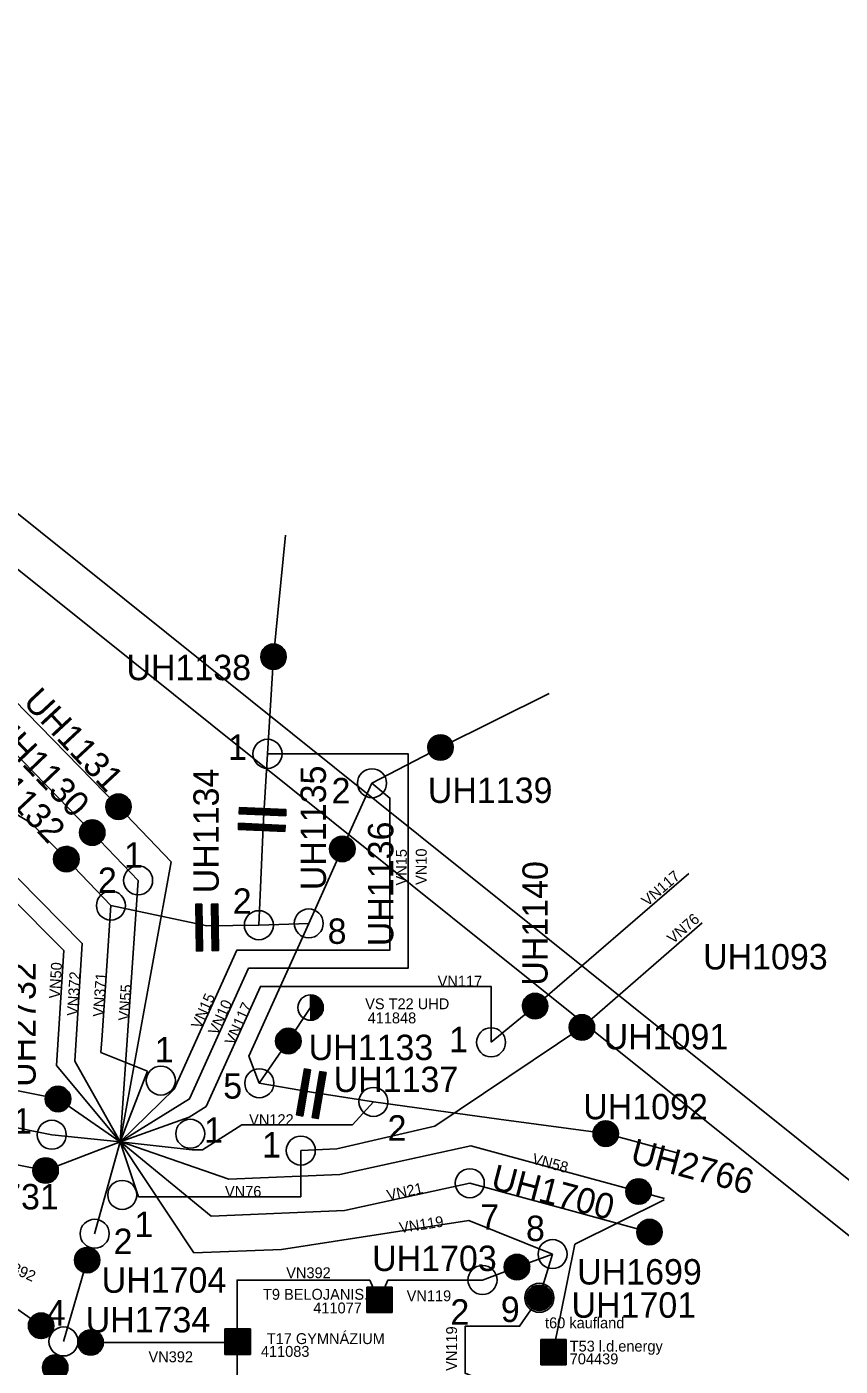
# Model space of a CAD drawing. Extents: x -541654 to -535721, y -1185255 to -1179094.
# Drawn here: x -537653 to -536532, y -1180940 to -1179094 of the extents above; entities that cross this region are included whole.
import ezdxf

# ---------------------------------------------------------------- set-up
doc = ezdxf.new("R2010")
doc.units = 0
for name, color, linetype in [('Default', 7, 'Continuous'), ('Vrstva 1', 7, 'Continuous'), ('Vrstva 2', 7, 'Continuous'), ('Vrstva 3', 7, 'Continuous'), ('Vrstva 5', 7, 'Continuous')]:
    doc.layers.add(name, color=color, linetype=linetype)

# ---------------------------------------------------------------- blocks, each defined once
blk = doc.blocks.new('PS100')
at = {"layer": 'Default'}
for p, q in [((-17.5, -0.7), (0.7, 17.5)), ((-17.5, 0.7), (-0.7, 17.5)), ((-17.4, -2), (2, 17.4)), ((-17.3, 2.2), (-2.2, 17.3)), ((-17.2, -3.3), (3.3, 17.2)), ((-17, 4), (-4, 17)), ((-16.9, -4.4), (4.4, 16.9)), ((-16.6, -5.5), (5.5, 16.6)), ((-16.4, 6), (-6, 16.4)), ((-16.2, -6.5), (6.5, 16.2)), ((-15.8, -7.5), (7.5, 15.8)), ((-15.3, -8.4), (8.4, 15.3)), ((-15.2, 8.6), (-8.6, 15.2)), ((-14.8, -9.3), (9.3, 14.8)), ((-14.2, -10.2), (10.2, 14.2)), ((-13.6, -11), (11, 13.6)), ((-13, -11.7), (11.7, 13)), ((-12.3, -12.5), (12.5, 12.3)), ((-11.5, -13.2), (13.2, 11.5)), ((-10.8, -13.8), (13.8, 10.8)), ((-9.9, -14.4), (14.4, 9.9)), ((-9.1, -14.9), (14.9, 9.1)), ((-8.2, -15.5), (15.5, 8.2)), ((-7.2, -15.9), (15.9, 7.2)), ((-6.2, -16.3), (16.3, 6.2)), ((-5.2, -16.7), (16.7, 5.2)), ((-4.1, -17), (17, 4.1)), ((-2.9, -17.2), (17.2, 2.9)), ((-1.6, -17.4), (17.4, 1.6)), ((-0.3, -17.5), (17.5, 0.3)), ((1.1, -17.4), (17.4, -1.1)), ((2.7, -17.3), (17.3, -2.7)), ((4.5, -16.9), (16.9, -4.5)), ((6.7, -16.2), (16.2, -6.7)), ((9.7, -14.5), (14.5, -9.7))]:
    blk.add_line(p, q, dxfattribs=at)
blk.add_circle((0, 0), 17.5, dxfattribs=at)
blk = doc.blocks.new('PS140')
at = {"layer": 'Default'}
for p, q in [((-17.5, 0), (0, 17.5)), ((-17.4, -1.4), (1.4, 17.4)), ((-17.4, 1.5), (-1.5, 17.4)), ((-17.3, -2.6), (2.6, 17.3)), ((-17.2, 3.1), (-3.1, 17.2)), ((-17.1, -3.8), (3.8, 17.1)), ((-16.8, -4.9), (4.9, 16.8)), ((-16.8, 5), (-5, 16.8)), ((-16.4, -6), (6, 16.4)), ((-16, -7), (7, 16)), ((-15.9, 7.2), (-7.2, 15.9)), ((-15.6, -8), (8, 15.6)), ((-15.1, -8.9), (8.9, 15.1)), ((-14.5, -9.8), (9.8, 14.5)), ((-13.9, -10.6), (10.6, 13.9)), ((-13.8, 10.8), (-10.8, 13.8)), ((-13.3, -11.4), (11.4, 13.3)), ((-12.6, -12.1), (12.1, 12.6)), ((-11.9, -12.8), (12.8, 11.9)), ((-11.2, -13.5), (13.5, 11.2)), ((-10.4, -14.1), (14.1, 10.4)), ((-9.5, -14.7), (14.7, 9.5)), ((-8.6, -15.2), (15.2, 8.6)), ((-7.7, -15.7), (15.7, 7.7)), ((-6.7, -16.1), (16.1, 6.7)), ((-5.7, -16.5), (16.5, 5.7)), ((-4.6, -16.9), (16.9, 4.6)), ((-3.5, -17.1), (17.1, 3.5)), ((-2.3, -17.3), (17.3, 2.3)), ((-1, -17.5), (17.5, 1)), ((0.4, -17.5), (17.5, -0.4)), ((1.9, -17.4), (17.4, -1.9)), ((3.6, -17.1), (17.1, -3.6)), ((5.5, -16.6), (16.6, -5.5)), ((8, -15.6), (15.6, -8))]:
    blk.add_line(p, q, dxfattribs=at)
blk.add_circle((0, 0), 17.5, dxfattribs=at)
blk = doc.blocks.new('PS150')
at = {"layer": 'Default'}
for p, q in [((-15.1, 22.4), (-7.4, 30.1)), ((-15.1, 23.8), (-8.8, 30.1)), ((-15.1, 25.2), (-10.2, 30.1)), ((-15.1, 26.6), (-11.6, 30.1)), ((-15.1, 28), (-13, 30.1)), ((-15.1, 29.4), (-14.4, 30.1)), ((-15.1, 20.9), (-6.5, 29.5)), ((-15.1, 19.5), (-6.5, 28.1)), ((-15.1, 18.1), (-6.5, 26.7)), ((-15.1, 16.7), (-6.5, 25.3)), ((-15.1, 15.3), (-6.5, 23.9)), ((-15.1, 13.9), (-6.5, 22.4)), ((-15.1, 12.5), (-6.5, 21)), ((-15.1, 11), (-6.5, 19.6)), ((6.7, 22.6), (14.1, 30.1)), ((6.7, 24), (12.7, 30.1)), ((6.7, 25.4), (11.3, 30.1)), ((6.7, 26.8), (9.9, 30.1)), ((6.7, 28.3), (8.5, 30.1)), ((6.7, 29.7), (7, 30.1)), ((6.7, 21.2), (15.2, 29.8)), ((6.7, 19.8), (15.2, 28.3)), ((6.7, 18.4), (15.2, 26.9)), ((6.7, 16.9), (15.2, 25.5)), ((6.7, 15.5), (15.2, 24.1)), ((6.7, 14.1), (15.2, 22.7)), ((6.7, 12.7), (15.2, 21.3)), ((6.7, 11.3), (15.2, 19.9)), ((-15.1, 9.6), (-6.5, 18.2)), ((-15.1, 8.2), (-6.5, 16.8)), ((-15.1, 6.8), (-6.5, 15.4)), ((-15.1, 5.4), (-6.5, 14)), ((-15.1, 4), (-6.5, 12.5)), ((-15.1, 2.6), (-6.5, 11.1)), ((-15.1, 1.2), (-6.5, 9.7)), ((-15.1, -0.3), (-6.5, 8.3)), ((-15.1, -1.7), (-6.5, 6.9)), ((-15.1, -3.1), (-6.5, 5.5)), ((-15.1, -4.5), (-6.5, 4.1)), ((-15.1, -5.9), (-6.5, 2.6)), ((-15.1, -7.3), (-6.5, 1.2)), ((6.7, 9.9), (15.2, 18.4)), ((6.7, 8.5), (15.2, 17)), ((6.7, 7.1), (15.2, 15.6)), ((6.7, 5.6), (15.2, 14.2)), ((6.7, 4.2), (15.2, 12.8)), ((6.7, 2.8), (15.2, 11.4)), ((6.7, 1.4), (15.2, 10)), ((6.7, 0), (15.2, 8.5)), ((6.7, -1.4), (15.2, 7.1)), ((6.7, -2.8), (15.2, 5.7)), ((6.7, -4.3), (15.2, 4.3)), ((6.7, -5.7), (15.2, 2.9)), ((6.7, -7.1), (15.2, 1.5)), ((6.7, -8.5), (15.2, 0.1)), ((-15.1, -8.7), (-6.5, -0.2)), ((-15.1, -10.2), (-6.5, -1.6)), ((-15.1, -11.6), (-6.5, -3)), ((-15.1, -13), (-6.5, -4.4)), ((-15.1, -14.4), (-6.5, -5.8)), ((-15.1, -15.8), (-6.5, -7.3)), ((-15.1, -17.2), (-6.5, -8.7)), ((-15.1, -18.6), (-6.5, -10.1)), ((-15.1, -20.1), (-6.5, -11.5)), ((-15.1, -21.5), (-6.5, -12.9)), ((-15.1, -22.9), (-6.5, -14.3)), ((-15.1, -24.3), (-6.5, -15.7)), ((-15.1, -25.7), (-6.5, -17.2)), ((6.7, -9.9), (15.2, -1.4)), ((6.7, -11.3), (15.2, -2.8)), ((6.7, -12.7), (15.2, -4.2)), ((6.7, -14.2), (15.2, -5.6)), ((6.7, -15.6), (15.2, -7)), ((6.7, -17), (15.2, -8.4)), ((6.7, -18.4), (15.2, -9.8)), ((6.7, -19.8), (15.2, -11.3)), ((6.7, -21.2), (15.2, -12.7)), ((6.7, -22.6), (15.2, -14.1)), ((6.7, -24.1), (15.2, -15.5)), ((6.7, -25.5), (15.2, -16.9)), ((6.7, -26.9), (15.2, -18.3)), ((-15.1, -27.1), (-6.5, -18.6)), ((-15.1, -28.5), (-6.5, -20)), ((-15.1, -30), (-6.5, -21.4)), ((-15.1, -31.4), (-6.5, -22.8)), ((-15.1, -32.8), (-6.5, -24.2)), ((-15, -34.2), (-6.5, -25.6)), ((-13.6, -34.2), (-6.5, -27.1)), ((-12.2, -34.2), (-6.5, -28.5)), ((-10.8, -34.2), (-6.5, -29.9)), ((-9.4, -34.2), (-6.5, -31.3)), ((-8, -34.2), (-6.5, -32.7)), ((-6.5, -34.2), (-6.5, -34.1)), ((6.7, -28.3), (15.2, -19.7)), ((6.7, -29.7), (15.2, -21.2)), ((6.7, -31.1), (15.2, -22.6)), ((6.7, -32.5), (15.2, -24)), ((6.7, -34), (15.2, -25.4)), ((7.9, -34.2), (15.2, -26.8)), ((9.3, -34.2), (15.2, -28.2)), ((10.7, -34.2), (15.2, -29.6)), ((12.1, -34.2), (15.2, -31)), ((13.5, -34.2), (15.2, -32.5)), ((14.9, -34.2), (15.2, -33.9))]:
    blk.add_line(p, q, dxfattribs=at)
for points in [[(-6.5, 30.1), (-6.5, -34.2), (-15.1, -34.2), (-15.1, 30.1)], [(15.2, 30.1), (15.2, -34.2), (6.7, -34.2), (6.7, 30.1)]]:
    blk.add_lwpolyline(points, close=True, dxfattribs=at)
blk = doc.blocks.new('PS610')
at = {"layer": 'Default'}
for p, q in [((0, 16.2), (1.3, 17.4)), ((0, 14.7), (2.5, 17.3)), ((0, 13.3), (3.7, 17.1)), ((0, 11.9), (4.9, 16.8)), ((0, 10.5), (5.9, 16.4)), ((0, 9.1), (7, 16)), ((0, 7.7), (7.9, 15.6)), ((0, 6.3), (8.8, 15.1)), ((0, 4.8), (9.7, 14.5)), ((0, 3.4), (10.5, 14)), ((0, 2), (11.3, 13.3)), ((0, 0.6), (12, 12.7)), ((0, -0.8), (12.8, 12)), ((0, -2.2), (13.4, 11.2)), ((0, -3.6), (14, 10.4)), ((0, -5), (14.6, 9.6)), ((0, -6.5), (15.2, 8.7)), ((0, -7.9), (15.6, 7.8)), ((0, -9.3), (16.1, 6.8)), ((0, -10.7), (16.5, 5.8)), ((0, -12.1), (16.8, 4.7)), ((0, -13.5), (17.1, 3.6)), ((0, -14.9), (17.3, 2.4)), ((0, -16.4), (17.4, 1.1)), ((0.3, -17.5), (17.5, -0.3)), ((1.8, -17.4), (17.4, -1.8)), ((3.5, -17.1), (17.1, -3.5)), ((5.4, -16.7), (16.7, -5.4)), ((7.8, -15.7), (15.6, -7.8))]:
    blk.add_line(p, q, dxfattribs=at)
blk.add_lwpolyline([(0, 17.5), (0, -17.5)], dxfattribs=at)
blk.add_circle((0, 0), 17.5, dxfattribs=at)
blk = doc.blocks.new('PS800')
at = {"layer": 'Vrstva 2'}
blk.add_circle((0, 0), 20, dxfattribs=at)
blk = doc.blocks.new('PS630')
at = {"layer": 'Default'}
for p, q in [((-16.6, -14.9), (17.1, 18.7)), ((-16.6, -13.5), (15.7, 18.7)), ((-16.6, -12.1), (14.2, 18.7)), ((-16.6, -10.7), (12.8, 18.7)), ((-16.6, -9.3), (11.4, 18.7)), ((-16.6, -7.9), (10, 18.7)), ((-16.6, -6.5), (8.6, 18.7)), ((-16.6, -5), (7.2, 18.7)), ((-16.6, -3.6), (5.8, 18.7)), ((-16.6, -2.2), (4.3, 18.7)), ((-16.6, -0.8), (2.9, 18.7)), ((-16.6, 0.6), (1.5, 18.7)), ((-16.6, 2), (0.1, 18.7)), ((-16.6, 3.4), (-1.3, 18.7)), ((-16.6, 4.9), (-2.7, 18.7)), ((-16.6, 6.3), (-4.1, 18.7)), ((-16.6, 7.7), (-5.6, 18.7)), ((-16.6, 9.1), (-7, 18.7)), ((-16.6, 10.5), (-8.4, 18.7)), ((-16.6, 11.9), (-9.8, 18.7)), ((-16.6, 13.3), (-11.2, 18.7)), ((-16.6, 14.8), (-12.6, 18.7)), ((-16.6, 16.2), (-14, 18.7)), ((-16.6, 17.6), (-15.5, 18.7)), ((-16.5, -16.3), (18.4, 18.6)), ((-15.1, -16.3), (18.4, 17.2)), ((-13.7, -16.3), (18.4, 15.8)), ((-12.3, -16.3), (18.4, 14.4)), ((-10.9, -16.3), (18.4, 13)), ((-9.4, -16.3), (18.4, 11.6)), ((-8, -16.3), (18.4, 10.2)), ((-6.6, -16.3), (18.4, 8.7)), ((-5.2, -16.3), (18.4, 7.3)), ((-3.8, -16.3), (18.4, 5.9)), ((-2.4, -16.3), (18.4, 4.5)), ((-1, -16.3), (18.4, 3.1)), ((0.5, -16.3), (18.4, 1.7)), ((1.9, -16.3), (18.4, 0.3)), ((3.3, -16.3), (18.4, -1.2)), ((4.7, -16.3), (18.4, -2.6)), ((6.1, -16.3), (18.4, -4)), ((7.5, -16.3), (18.4, -5.4)), ((8.9, -16.3), (18.4, -6.8)), ((10.4, -16.3), (18.4, -8.2)), ((11.8, -16.3), (18.4, -9.6)), ((13.2, -16.3), (18.4, -11.1)), ((14.6, -16.3), (18.4, -12.5)), ((16, -16.3), (18.4, -13.9)), ((17.4, -16.3), (18.4, -15.3))]:
    blk.add_line(p, q, dxfattribs=at)
for points in [[(-16.6, 18.7), (-16.6, -16.3)], [(18.4, 18.7), (-16.6, 18.7)], [(-16.6, 18.7), (-16.6, -16.3)], [(18.4, -16.3), (18.4, 18.7)], [(-16.6, -16.3), (18.4, -16.3)]]:
    blk.add_lwpolyline(points, dxfattribs=at)

msp = doc.modelspace()

# ---------------------------------------------------------------- linework, layer by layer
at = {"layer": 'Default'}
for points in [[(-535721.4, -1181322.7), (-538502.4, -1179093.8), (-541654.5, -1183026.4), (-538873.5, -1185255.4)], [(-535805.8, -1181332), (-538493.1, -1179178.1), (-541570.1, -1183017.1), (-538882.8, -1185171.1)]]:
    msp.add_lwpolyline(points, close=True, dxfattribs=at)
at = {"layer": 'Vrstva 1'}
for points in [[(-537562.4, -1180204.4), (-538043.7, -1179710), (-538197.4, -1179520.6)], [(-537976.7, -1179707), (-537526.2, -1180168.7)], [(-537312.6, -1179962), (-537295.9, -1179794.3)], [(-537312.6, -1179962), (-537320.9, -1180095.8)], [(-537082.5, -1180087.1), (-536932.8, -1180012.7)], [(-537523.8, -1180630.5), (-537428.2, -1180571.4), (-537346.9, -1180391.3), (-537127.1, -1180391.3), (-537127.1, -1180095.8), (-537320.9, -1180095.8)], [(-537326.2, -1180186.4), (-537320.9, -1180095.8)], [(-537176.9, -1180136.3), (-537082.5, -1180087.1)], [(-537449.6, -1180558.2), (-537363, -1180366.3), (-537152.1, -1180366.3), (-537152.1, -1180156.7), (-537176.9, -1180136.3)], [(-537176.9, -1180136.3), (-537217.8, -1180226.9), (-537217.8, -1180226.9)], [(-537646.5, -1180191.3), (-537693.8, -1180162.8)], [(-537526.2, -1180168.7), (-537453.8, -1180244.5)], [(-537753.3, -1180178.2), (-537576.2, -1180357.2), (-537586.3, -1180519.6), (-537523.8, -1180630.5)], [(-537598.1, -1180240.9), (-537646.5, -1180191.3)], [(-537332.8, -1180332), (-537326.2, -1180186.4)], [(-537562.4, -1180204.4), (-537499.2, -1180270.2)], [(-537217.8, -1180226.9), (-537264.1, -1180329.5)], [(-537536.7, -1180305), (-537598.1, -1180240.9)], [(-537453.8, -1180244.5), (-537523.8, -1180630.5)], [(-536952.1, -1180443.4), (-536740.1, -1180260.9)], [(-537523.8, -1180630.5), (-537499.2, -1180270.2)], [(-537677.7, -1180290.2), (-537601.8, -1180366.9), (-537611.7, -1180525.5), (-537523.8, -1180630.5)], [(-537542.6, -1180394.7), (-537536.7, -1180305)], [(-537536.7, -1180305), (-537404.3, -1180333)], [(-537404.3, -1180333), (-537332.8, -1180332)], [(-537264.1, -1180329.5), (-537346.8, -1180512.5), (-537332.2, -1180549.8)], [(-537332.8, -1180332), (-537264.1, -1180329.5)], [(-536721.7, -1180328.9), (-536887.6, -1180472.8)], [(-537548.7, -1180483.8), (-537542.6, -1180394.7)], [(-537428.9, -1180596.7), (-537405.5, -1180581.7), (-537330.7, -1180416.3), (-537012.8, -1180416.3), (-537012.8, -1180493.4)], [(-537261.5, -1180445.6), (-537292.2, -1180491.6)], [(-537012.8, -1180493.4), (-536952.1, -1180443.4)], [(-537609.6, -1180571.5), (-538081.7, -1180476.7)], [(-537550.4, -1180507.5), (-537548.7, -1180483.8)], [(-536887.6, -1180472.8), (-537090.3, -1180608.8), (-537225.5, -1180640.2), (-537275, -1180642.6)], [(-537486.4, -1180533.1), (-537550.4, -1180507.5)], [(-537292.2, -1180491.6), (-537332.2, -1180549.8)], [(-537618.2, -1180620.8), (-538091, -1180525.9)], [(-537486.4, -1180533.1), (-537523.8, -1180630.5)], [(-537449.6, -1180558.2), (-537523.8, -1180630.5)], [(-537332.2, -1180549.8), (-537260.2, -1180562.3)], [(-537260.2, -1180562.3), (-537174.9, -1180575.5)], [(-537626.7, -1180670.1), (-538100, -1180575)], [(-537609.6, -1180571.5), (-537523.8, -1180630.5)], [(-537424.9, -1180641.5), (-537410.4, -1180641.5), (-537356.4, -1180607), (-537203.9, -1180607), (-537174.9, -1180575.5)], [(-537174.9, -1180575.5), (-537002.3, -1180599.1)], [(-537428.9, -1180596.7), (-537523.8, -1180630.5)], [(-537002.3, -1180599.1), (-536854.8, -1180619.3)], [(-536854.8, -1180619.3), (-536755, -1180646.2)], [(-537626.7, -1180670.1), (-537523.8, -1180630.5)], [(-537618.2, -1180620.8), (-537523.8, -1180630.5)], [(-537523.8, -1180630.5), (-537559.1, -1180757.2)], [(-537398.4, -1180732.8), (-537523.8, -1180630.2)], [(-537374.2, -1180682), (-537523.8, -1180630.2)], [(-537424.9, -1180641.5), (-537523.8, -1180630.5)], [(-537422.6, -1180783.7), (-537523.8, -1180630.5)], [(-537523.8, -1180630.5), (-537498.9, -1180706.2)], [(-537374.2, -1180682), (-537221.1, -1180675.5), (-537040.8, -1180636.2)], [(-537040.8, -1180636.2), (-536809.5, -1180699)], [(-537498.9, -1180706.2), (-537275, -1180706.2), (-537275, -1180642.6)], [(-537398.4, -1180732.8), (-537214.9, -1180725.3), (-537042.1, -1180687.6)], [(-537042.1, -1180687.6), (-536898.5, -1180726.7)], [(-536774.3, -1180710.6), (-536897.2, -1180771.6), (-536927.8, -1180921.8)], [(-536809.5, -1180699), (-536773.7, -1180708.6)], [(-536898.5, -1180726.7), (-536794.5, -1180754.9)], [(-537422.6, -1180783.7), (-537301.8, -1180778.9), (-537043.4, -1180739.1), (-536928, -1180785.3)], [(-536794.5, -1180754.9), (-536788.1, -1180756.6)], [(-536928, -1180785.3), (-536977.1, -1180803.2)], [(-536928, -1180785.3), (-536946.3, -1180845.5)], [(-537569.4, -1180793.6), (-537602.1, -1180905.7)], [(-536977.1, -1180803.2), (-537024.6, -1180821)], [(-537362.9, -1180907.2), (-537362.9, -1180821), (-537180, -1180821), (-537167.5, -1180849.6)], [(-537167.5, -1180849.6), (-537155, -1180821), (-537024.6, -1180821)], [(-537632.9, -1180884), (-537693.1, -1180842.2)], [(-536946.3, -1180845.5), (-536973.5, -1180884.8), (-537048.7, -1180884.8), (-537048.7, -1180949.6), (-537017.9, -1180962.1)], [(-537564.7, -1180907.2), (-537463.8, -1180907.2)], [(-537463.8, -1180907.2), (-537362.9, -1180907.2)], [(-537266.6, -1180972.8), (-537362.9, -1180972.8), (-537362.9, -1180907.2)]]:
    msp.add_lwpolyline(points, dxfattribs=at)

# ---------------------------------------------------------------- block references
at = {"layer": 'Vrstva 2'}
for name, p, rotation in [('PS140', (-537312.6, -1179962), 79.66586668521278), ('PS140', (-537082.5, -1180087.1), 35.23704443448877), ('PS140', (-537526.2, -1180168.7), -49.236283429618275), ('PS150', (-537326.2, -1180186.4), -92.58337939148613), ('PS140', (-537562.4, -1180204.4), -49.669405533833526), ('PS140', (-537217.8, -1180226.9), 66.80257499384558), ('PS140', (-537598.1, -1180240.9), -48.565561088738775), ('PS150', (-537404.3, -1180333), 0.7996121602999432), ('PS140', (-536952.1, -1180443.4), 43.197147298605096), ('PS140', (-536887.6, -1180472.8), 29.7465250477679), ('PS140', (-537292.2, -1180491.6), 45.90339991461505), ('PS150', (-537260.2, -1180562.3), -9.49041953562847), ('PS100', (-537609.6, -1180571.5), 29.01520613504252), ('PS140', (-536854.8, -1180619.3), -14.905680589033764), ('PS100', (-537626.7, -1180670.1), -108.56155173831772), ('PS140', (-536809.5, -1180699), -12.072944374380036), ('PS140', (-536794.5, -1180754.9), -32.633916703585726), ('PS140', (-537569.4, -1180793.6), 151.37969727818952), ('PS140', (-536977.1, -1180803.2), 64.36294440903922), ('PS140', (-536946.3, -1180845.5), 85.87850277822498), ('PS140', (-537632.9, -1180884), 104.28510836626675), ('PS140', (-537564.7, -1180907.2), -96.73781112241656), ('PS140', (-537613.4, -1180941.7), 105.13879994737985)]:
    msp.add_blockref(name, p, dxfattribs=dict(at, rotation=rotation))
at = {"layer": 'Vrstva 3', "rotation": 0.6231999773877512}
msp.add_blockref('PS610', (-537261.5, -1180445.6), dxfattribs=at)
at = {"layer": 'Vrstva 3'}
for p in [(-537167.5, -1180849.6), (-537362.9, -1180907.2), (-536927.8, -1180921.8)]:
    msp.add_blockref('PS630', p, dxfattribs=at)
at = {"layer": 'Vrstva 5'}
for p, rotation in [((-537320.9, -1180095.8), 79.66586668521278), ((-537176.9, -1180136.3), 56.33263605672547), ((-537499.2, -1180270.2), 130.68397226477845), ((-537536.7, -1180305), 131.57130551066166), ((-537332.8, -1180332), 17.869624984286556), ((-537264.1, -1180329.5), 81.62706113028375), ((-537012.8, -1180493.4), 64.92728603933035), ((-537467.9, -1180546.2), 54.3026055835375), ((-537332.2, -1180549.8), 62.541836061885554), ((-537174.9, -1180575.5), -9.04878329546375), ((-537618.2, -1180620.8), 78.12650001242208), ((-537427.3, -1180619.4), 67.58060838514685), ((-537275, -1180642.6), 104.27390276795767), ((-537042.1, -1180687.6), 10.448444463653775), ((-537521.1, -1180703.7), 54.32645558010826), ((-537559.1, -1180757.2), -3.9367750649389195), ((-536928, -1180785.3), -18.51338601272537), ((-537024.6, -1180821), 1.2024888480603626), ((-536946.3, -1180845.5), 83.83051388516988), ((-537602.1, -1180905.7), 48.59803887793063)]:
    msp.add_blockref('PS800', p, dxfattribs=dict(at, rotation=rotation))

# ---------------------------------------------------------------- texts
at = {"layer": 'Vrstva 1'}
for s, rotation, p in [('VN15', 90, (-537128.9, -1180277.2)), ('VN10', 90, (-537101.5, -1180276.5)), ('VN117', 40.735, (-536797.5, -1180306.8)), ('VN76', 40.936, (-536762.1, -1180358.6)), ('VN50', 86.443, (-537607.1, -1180433.6)), ('VN372', 86.443, (-537582.4, -1180457.5)), ('VN371', 86.053, (-537546.7, -1180458.9)), ('VN55', 86.053, (-537511.4, -1180464.1)), ('VN15', 65.736, (-537413.3, -1180476.1)), ('VN10', 65.694, (-537389.7, -1180484.8)), ('VN117', 65.694, (-537366.9, -1180498.6)), ('VN122', 359.991, (-537346.2, -1180607.5)), ('VN58', 344.803, (-536957.3, -1180660.5)), ('VN76', 0.008, (-537379.5, -1180706.4)), ('VN21', 12.303, (-537154.6, -1180711.8)), ('VN119', 8.639, (-537138.1, -1180756.5)), ('VN392', 335.828, (-537700.7, -1180798.6)), ('VN119', 90, (-537059.7, -1180946.2))]:
    msp.add_text(s, height=15, rotation=rotation, dxfattribs=at).set_placement(p)
for s, p in [('VN117', (-537086.4, -1180416.6)), ('VN392', (-537295.1, -1180818.5)), ('VN119', (-537129.1, -1180850.3)), ('VN392', (-537484.9, -1180934.3))]:
    msp.add_text(s, height=15, dxfattribs=at).set_placement(p)
at = {"layer": 'Vrstva 2'}
for s, p in [('UH1138', (-537515.3, -1179994.3)), ('UH1139', (-537099.9, -1180163.5)), ('UH1093', (-536720.6, -1180393)), ('UH1091', (-536857.7, -1180503.1)), ('UH1133', (-537264.2, -1180517.9)), ('UH1137', (-537229.7, -1180561.9)), ('UH1092', (-536885.8, -1180599.5)), ('UH2731', (-537780.2, -1180723.7)), ('UH1703', (-537176.7, -1180808.6)), ('UH1704', (-537549.4, -1180838.6)), ('UH1699', (-536894.1, -1180827.2)), ('UH1701', (-536901.9, -1180873)), ('UH1734', (-537571.5, -1180893.3))]:
    msp.add_text(s, height=35, dxfattribs=at).set_placement(p)
for s, rotation, p in [('UH1131', 312.966, (-537659.2, -1180025.3)), ('UH1130', 313.698, (-537707.2, -1180061.8)), ('UH1132', 313.059, (-537739.6, -1180096)), ('UH1134', 89.967, (-537388.1, -1180288)), ('UH1135', 90, (-537240.4, -1180283.7)), ('UH1136', 90, (-537147.5, -1180360.9)), ('UH1140', 89.85, (-536935, -1180415.4)), ('UH2732', 90, (-537640.4, -1180554.8)), ('UH2766', 345.07, (-536822.5, -1180659.3)), ('UH1700', 345.316, (-537014.8, -1180695))]:
    msp.add_text(s, height=35, rotation=rotation, dxfattribs=at).set_placement(p)
at = {"layer": 'Vrstva 3'}
for s, p in [('VS T22 UHD', (-537186.3, -1180447.8)), ('411848', (-537182.9, -1180467.3)), ('T9 BELOJANIS.', (-537327.1, -1180848.2)), ('411077', (-537257.8, -1180867)), ('t60 kaufland', (-536938.4, -1180887.5)), ('T17 GYMNÁZIUM', (-537321.9, -1180909.3)), ('411083', (-537330, -1180926.9)), ('T53 l.d.energy', (-536904.4, -1180919.6)), ('704439', (-536904.4, -1180937.2))]:
    msp.add_text(s, height=15, dxfattribs=at).set_placement(p)
at = {"layer": 'Vrstva 5'}
for s, p in [('1', (-537375.4, -1180104.1)), ('2', (-537232.6, -1180164)), ('1', (-537518.4, -1180252.6)), ('2', (-537554.6, -1180287.5)), ('2', (-537368.8, -1180316.3)), ('8', (-537238, -1180357.7)), ('1', (-537070.5, -1180507)), ('1', (-537476.3, -1180521.2)), ('5', (-537381.9, -1180571)), ('1', (-537671.6, -1180619.2)), ('1', (-537408.1, -1180631.7)), ('2', (-537155.4, -1180628.9)), ('1', (-537328.3, -1180652.2)), ('1', (-537504.3, -1180761.7)), ('7', (-537027.7, -1180751.5)), ('8', (-536964.7, -1180767.3)), ('2', (-537533, -1180785.2)), ('4', (-537625.3, -1180883.7)), ('2', (-537068.8, -1180882.5)), ('9', (-536999.3, -1180878.9))]:
    msp.add_text(s, height=35, dxfattribs=at).set_placement(p)

doc.saveas('drawing.dxf')
